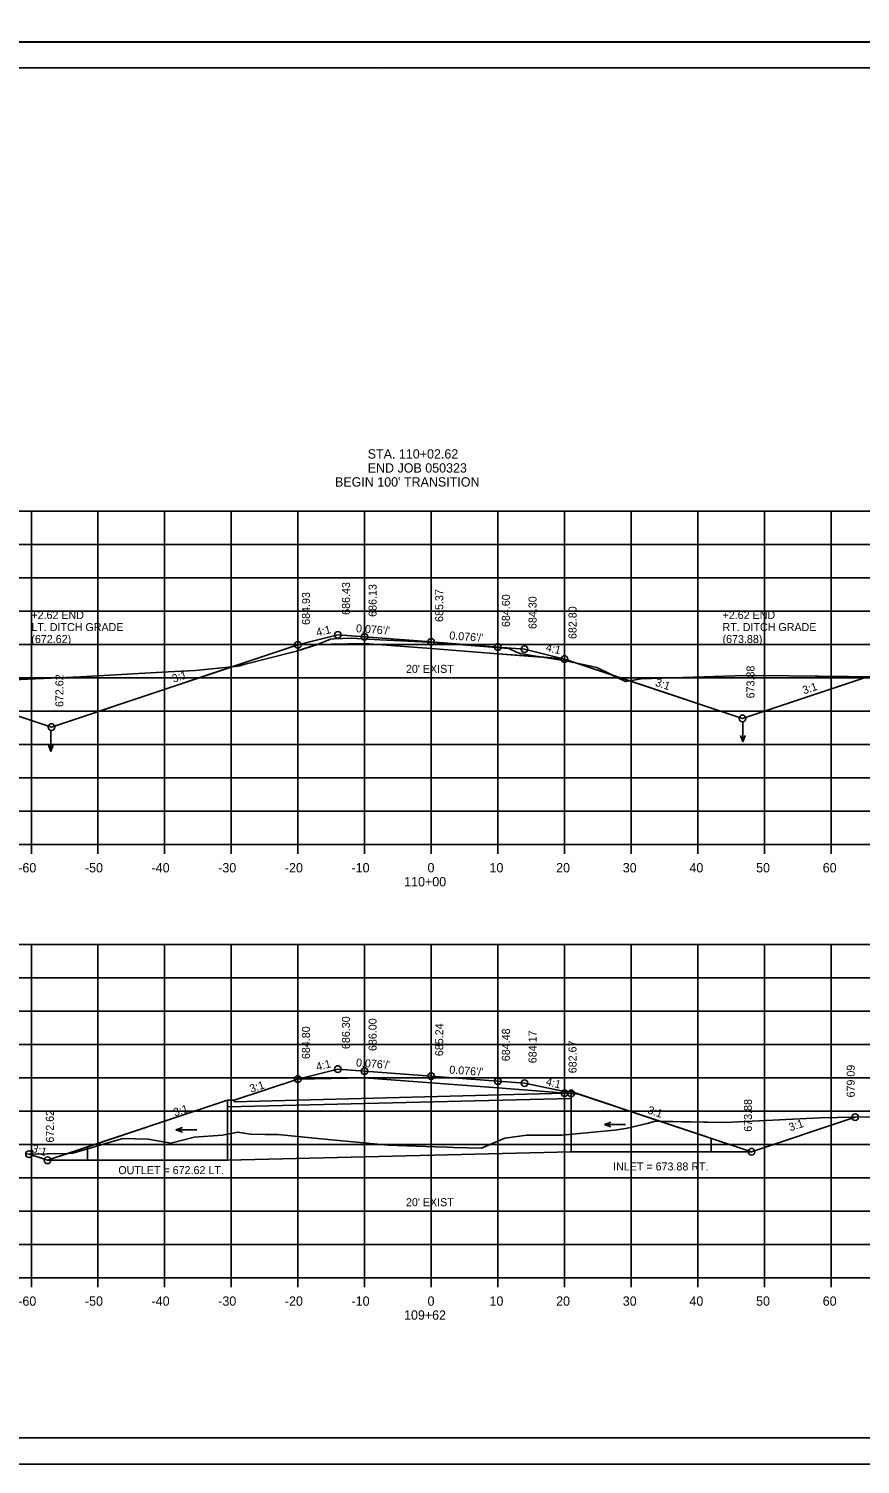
# Model space of a CAD drawing. Extents: x 1360146 to 1361431, y 631444 to 632352.
# Drawn here: x 1360258.4 to 1360383.1, y 631870.8 to 632086.2 of the extents above; entities that cross this region are included whole.
import ezdxf

# ---------------------------------------------------------------- set-up
doc = ezdxf.new("R2010")
doc.units = 0
for name, color, linetype in [('Default', 7, 'Continuous'), ('R_Alt Surface', 7, 'Continuous'), ('R_Axis', 7, 'Continuous'), ('R_Axis Annot', 7, 'Continuous'), ('R_Border', 7, 'Continuous'), ('R_Exist Surface', 7, 'Continuous'), ('R_Fin Surface', 7, 'Continuous'), ('R_Grid', 7, 'Continuous'), ('R_No Plot', 7, 'Continuous'), ('R_Water', 7, 'Continuous'), ('R_Water Annot', 7, 'Continuous'), ('R_Xsect Elev', 7, 'Continuous'), ('R_Xsect Slope', 7, 'Continuous')]:
    doc.layers.add(name, color=color, linetype=linetype)

msp = doc.modelspace()

# ---------------------------------------------------------------- linework, layer by layer
at = {"layer": 'Default'}
for p, q in [((1360308.77, 631988.16), (1360308.77, 631989.53)), ((1360308.77, 631988.82), (1360328.77, 631988.82)), ((1360328.77, 631988.16), (1360328.77, 631989.53)), ((1360332.77, 631927.99), (1360338.77, 631926.74)), ((1360288.2, 631925.43), (1360289.2, 631925.43)), ((1360366.83, 631917.72), (1360382.39, 631922.91)), ((1360308.77, 631908.16), (1360308.77, 631909.53)), ((1360308.77, 631908.82), (1360328.77, 631908.82)), ((1360328.77, 631908.16), (1360328.77, 631909.53))]:
    msp.add_line(p, q, dxfattribs=at)
at = {"layer": 'R_Alt Surface'}
for points in [[(1360298.75, 631993.74), (1360308.77, 631993.94), (1360318.77, 631993.19), (1360328.77, 631992.42), (1360338.55, 631991.67)], [(1360298.75, 631928.61), (1360308.77, 631928.81), (1360318.77, 631928.06), (1360328.77, 631927.29), (1360340.89, 631926.37)]]:
    msp.add_lwpolyline(points, dxfattribs=at)
at = {"layer": 'R_Axis'}
for p, q in [((1360178.77, 631963.82), (1360458.77, 631963.82)), ((1360258.77, 631962.42), (1360258.77, 631963.82)), ((1360268.77, 631962.42), (1360268.77, 631963.82)), ((1360278.77, 631962.42), (1360278.77, 631963.82)), ((1360288.77, 631962.42), (1360288.77, 631963.82)), ((1360298.77, 631962.42), (1360298.77, 631963.82)), ((1360308.77, 631962.42), (1360308.77, 631963.82)), ((1360318.77, 631962.42), (1360318.77, 631963.82)), ((1360328.77, 631962.42), (1360328.77, 631963.82)), ((1360338.77, 631962.42), (1360338.77, 631963.82)), ((1360348.77, 631962.42), (1360348.77, 631963.82)), ((1360358.77, 631962.42), (1360358.77, 631963.82)), ((1360368.77, 631962.42), (1360368.77, 631963.82)), ((1360378.77, 631962.42), (1360378.77, 631963.82)), ((1360178.77, 631898.82), (1360458.77, 631898.82)), ((1360258.77, 631897.42), (1360258.77, 631898.82)), ((1360268.77, 631897.42), (1360268.77, 631898.82)), ((1360278.77, 631897.42), (1360278.77, 631898.82)), ((1360288.77, 631897.42), (1360288.77, 631898.82)), ((1360298.77, 631897.42), (1360298.77, 631898.82)), ((1360308.77, 631897.42), (1360308.77, 631898.82)), ((1360318.77, 631897.42), (1360318.77, 631898.82)), ((1360328.77, 631897.42), (1360328.77, 631898.82)), ((1360338.77, 631897.42), (1360338.77, 631898.82)), ((1360348.77, 631897.42), (1360348.77, 631898.82)), ((1360358.77, 631897.42), (1360358.77, 631898.82)), ((1360368.77, 631897.42), (1360368.77, 631898.82)), ((1360378.77, 631897.42), (1360378.77, 631898.82))]:
    msp.add_line(p, q, dxfattribs=at)
at = {"layer": 'R_Border'}
for p, q in [((1360158.77, 632080.28), (1360474.95, 632080.28)), ((1360311.29, 632080.02), (1360311.29, 632080.02)), ((1360311.29, 632080.02), (1360311.29, 632080.02)), ((1360474.95, 631874.82), (1360158.77, 631874.82))]:
    msp.add_line(p, q, dxfattribs=at)
at = {"layer": 'R_Exist Surface'}
for points in [[(1360236.74, 631987.68), (1360260.53, 631988.72), (1360260.57, 631988.72), (1360260.61, 631988.72), (1360266.15, 631988.93), (1360279.32, 631989.69), (1360283.36, 631989.88), (1360289.35, 631990.49), (1360290.04, 631990.61), (1360290.65, 631990.81), (1360298.57, 631992.8), (1360301.69, 631993.82), (1360303.67, 631994.61), (1360304.16, 631994.65), (1360306.77, 631994.73), (1360311.04, 631994.52), (1360318.39, 631994.15), (1360322.84, 631993.81), (1360330.41, 631993.2), (1360331.57, 631992.65), (1360332.16, 631992.47), (1360334.1, 631992.09), (1360339.03, 631991.36), (1360343.63, 631990.34), (1360347.93, 631988.25), (1360350.29, 631988.65), (1360365.94, 631989.14), (1360372.41, 631989.11), (1360390.37, 631988.9)], [(1360258.06, 631917.36), (1360264.29, 631917.44), (1360265, 631917.52), (1360272.51, 631919.69), (1360276.32, 631919.58), (1360279.68, 631919.01), (1360283.22, 631919.92), (1360287.46, 631920.21), (1360289.76, 631920.67), (1360291.64, 631920.33), (1360293.78, 631920.28), (1360295.75, 631920.3), (1360302.24, 631919.66), (1360312.29, 631918.68), (1360319.35, 631918.47), (1360321.14, 631918.41), (1360322.11, 631918.37), (1360326.32, 631918.24), (1360329.8, 631919.77), (1360333.12, 631920.2), (1360333.65, 631920.19), (1360338.39, 631920.2), (1360346.26, 631920.97), (1360347.95, 631921.21), (1360351.15, 631921.96), (1360352.42, 631922.28), (1360362.86, 631922.12), (1360377.14, 631922.78), (1360387.04, 631923.01)]]:
    msp.add_lwpolyline(points, dxfattribs=at)
at = {"layer": 'R_Fin Surface'}
for points in [[(1360242.28, 631987.92), (1360261.78, 631981.42), (1360298.75, 631993.74), (1360298.77, 631993.75), (1360304.77, 631995.25), (1360308.77, 631994.95), (1360318.77, 631994.19), (1360328.77, 631993.42), (1360332.77, 631993.12), (1360338.55, 631991.67), (1360338.77, 631991.62), (1360365.47, 631982.72), (1360384.22, 631988.97)], [(1360258.42, 631917.36), (1360261.2, 631916.43), (1360288.2, 631925.43), (1360289.2, 631925.43), (1360298.75, 631928.61), (1360298.77, 631928.62), (1360304.77, 631930.12), (1360308.77, 631929.82), (1360318.77, 631929.06), (1360328.77, 631928.3), (1360332.77, 631927.99), (1360338.77, 631926.74), (1360339.77, 631926.74), (1360366.83, 631917.72), (1360382.39, 631922.91)]]:
    msp.add_lwpolyline(points, dxfattribs=at)
at = {"layer": 'R_Grid'}
for p, q in [((1360178.77, 632013.82), (1360458.77, 632013.82)), ((1360258.77, 631963.82), (1360258.77, 632013.82)), ((1360268.77, 631963.82), (1360268.77, 632013.82)), ((1360278.77, 631963.82), (1360278.77, 632013.82)), ((1360288.77, 631963.82), (1360288.77, 632013.82)), ((1360298.77, 631963.82), (1360298.77, 632013.82)), ((1360308.77, 631963.82), (1360308.77, 632013.82)), ((1360318.77, 631963.82), (1360318.77, 632013.82)), ((1360328.77, 631963.82), (1360328.77, 632013.82)), ((1360338.77, 631963.82), (1360338.77, 632013.82)), ((1360348.77, 631963.82), (1360348.77, 632013.82)), ((1360358.77, 631963.82), (1360358.77, 632013.82)), ((1360368.77, 631963.82), (1360368.77, 632013.82)), ((1360378.77, 631963.82), (1360378.77, 632013.82)), ((1360178.77, 632008.82), (1360458.77, 632008.82)), ((1360178.77, 632003.82), (1360458.77, 632003.82)), ((1360178.77, 631998.82), (1360458.77, 631998.82)), ((1360178.77, 631993.82), (1360458.77, 631993.82)), ((1360178.77, 631988.82), (1360458.77, 631988.82)), ((1360178.77, 631983.82), (1360458.77, 631983.82)), ((1360178.77, 631978.82), (1360458.77, 631978.82)), ((1360178.77, 631973.82), (1360458.77, 631973.82)), ((1360178.77, 631968.82), (1360458.77, 631968.82)), ((1360178.77, 631963.82), (1360458.77, 631963.82)), ((1360178.77, 631948.82), (1360458.77, 631948.82)), ((1360258.77, 631898.82), (1360258.77, 631948.82)), ((1360268.77, 631898.82), (1360268.77, 631948.82)), ((1360278.77, 631898.82), (1360278.77, 631948.82)), ((1360288.77, 631898.82), (1360288.77, 631948.82)), ((1360298.77, 631898.82), (1360298.77, 631948.82)), ((1360308.77, 631898.82), (1360308.77, 631948.82)), ((1360318.77, 631898.82), (1360318.77, 631948.82)), ((1360328.77, 631898.82), (1360328.77, 631948.82)), ((1360338.77, 631898.82), (1360338.77, 631948.82)), ((1360348.77, 631898.82), (1360348.77, 631948.82)), ((1360358.77, 631898.82), (1360358.77, 631948.82)), ((1360368.77, 631898.82), (1360368.77, 631948.82)), ((1360378.77, 631898.82), (1360378.77, 631948.82)), ((1360178.77, 631943.82), (1360458.77, 631943.82)), ((1360178.77, 631938.82), (1360458.77, 631938.82)), ((1360178.77, 631933.82), (1360458.77, 631933.82)), ((1360178.77, 631928.82), (1360458.77, 631928.82)), ((1360178.77, 631923.82), (1360458.77, 631923.82)), ((1360178.77, 631918.82), (1360458.77, 631918.82)), ((1360178.77, 631913.82), (1360458.77, 631913.82)), ((1360178.77, 631908.82), (1360458.77, 631908.82)), ((1360178.77, 631903.82), (1360458.77, 631903.82)), ((1360178.77, 631898.82), (1360458.77, 631898.82))]:
    msp.add_line(p, q, dxfattribs=at)
at = {"layer": 'R_No Plot'}
for p, q in [((1360146.37, 632084.18), (1360479.7, 632084.18)), ((1360146.37, 632084.17), (1360479.7, 632084.17)), ((1360146.37, 631870.84), (1360479.7, 631870.84))]:
    msp.add_line(p, q, dxfattribs=at)
for points in [[(1360146.36, 632297.51), (1360479.7, 632297.51), (1360479.7, 632084.17), (1360146.36, 632084.17)], [(1360146.36, 632084.17), (1360479.7, 632084.17), (1360479.7, 631870.84), (1360146.36, 631870.84)], [(1360392.69, 632080.28), (1360392.69, 632070.4), (1360428.42, 632070.4), (1360428.42, 632067.48), (1360451.62, 632067.48), (1360451.62, 632043.15), (1360474.95, 632043.15), (1360474.95, 631874.82), (1360158.77, 631874.82), (1360158.77, 632080.28)], [(1360288.84, 631990.44), (1360289.35, 631990.49), (1360290.04, 631990.61), (1360290.65, 631990.81), (1360298.57, 631992.8), (1360301.63, 631993.8), (1360298.75, 631993.74)], [(1360301.63, 631993.8), (1360301.69, 631993.82), (1360303.67, 631994.61), (1360304.16, 631994.65), (1360306.77, 631994.73), (1360311.04, 631994.52), (1360318.39, 631994.15), (1360322.84, 631993.81), (1360330.41, 631993.2), (1360331.57, 631992.65), (1360332.16, 631992.47), (1360334.1, 631992.09), (1360335.14, 631991.94), (1360328.77, 631992.42), (1360318.77, 631993.19), (1360308.77, 631993.94)], [(1360335.14, 631991.94), (1360339.03, 631991.36), (1360340.59, 631991.02), (1360338.77, 631991.62), (1360338.55, 631991.67)], [(1360340.59, 631991.02), (1360343.63, 631990.34), (1360345.83, 631989.27)], [(1360242.28, 631987.92), (1360260.53, 631988.72), (1360260.57, 631988.72), (1360260.61, 631988.72), (1360266.15, 631988.93), (1360279.32, 631989.69), (1360283.36, 631989.88), (1360288.84, 631990.44), (1360261.78, 631981.42)], [(1360345.83, 631989.27), (1360347.93, 631988.25), (1360348.56, 631988.36)], [(1360348.56, 631988.36), (1360350.29, 631988.65), (1360365.94, 631989.14), (1360372.41, 631989.11), (1360384.22, 631988.97), (1360365.47, 631982.72)], [(1360264.23, 631917.44), (1360264.29, 631917.44), (1360265, 631917.52), (1360272.51, 631919.69), (1360276.32, 631919.58), (1360279.68, 631919.01), (1360283.22, 631919.92), (1360287.46, 631920.21), (1360289.76, 631920.67), (1360291.64, 631920.33), (1360293.78, 631920.28), (1360295.75, 631920.3), (1360302.24, 631919.66), (1360312.29, 631918.68), (1360319.35, 631918.47), (1360321.14, 631918.41), (1360322.11, 631918.37), (1360326.32, 631918.24), (1360329.8, 631919.77), (1360333.12, 631920.2), (1360333.65, 631920.19), (1360338.39, 631920.2), (1360346.26, 631920.97), (1360347.95, 631921.21), (1360351.15, 631921.96), (1360352.42, 631922.28), (1360353.18, 631922.27), (1360340.89, 631926.37), (1360328.77, 631927.29), (1360318.77, 631928.06), (1360308.77, 631928.81), (1360298.75, 631928.61), (1360289.2, 631925.43), (1360288.2, 631925.43)], [(1360353.18, 631922.27), (1360362.86, 631922.12), (1360377.14, 631922.78), (1360382.39, 631922.91), (1360366.83, 631917.72)], [(1360258.42, 631917.36), (1360264.23, 631917.44), (1360261.2, 631916.43)]]:
    msp.add_lwpolyline(points, close=True, dxfattribs=at)
for centre in [(1360304.77, 631995.25), (1360308.77, 631994.95), (1360298.77, 631993.75), (1360318.77, 631994.19), (1360328.77, 631993.42), (1360332.77, 631993.12), (1360338.77, 631991.62), (1360365.47, 631982.72), (1360261.78, 631981.42), (1360304.77, 631930.12), (1360298.77, 631928.62), (1360308.77, 631929.82), (1360318.77, 631929.06), (1360328.77, 631928.3), (1360332.77, 631927.99), (1360338.77, 631926.49), (1360339.77, 631926.47), (1360382.39, 631922.91), (1360258.42, 631917.36), (1360366.83, 631917.72), (1360261.2, 631916.43)]:
    msp.add_circle(centre, 0.5, dxfattribs=at)
at = {"layer": 'R_Water'}
for p, q in [((1360338.77, 631926.49), (1360289.2, 631925.18)), ((1360338.77, 631926.49), (1360338.77, 631926.74)), ((1360338.77, 631926.74), (1360339.77, 631926.74)), ((1360338.77, 631926.74), (1360339.77, 631926.74)), ((1360366.83, 631917.72), (1360339.77, 631926.74)), ((1360339.77, 631917.74), (1360339.77, 631926.74)), ((1360261.2, 631916.43), (1360288.2, 631925.43)), ((1360339.77, 631925.72), (1360288.2, 631924.47)), ((1360288.2, 631916.43), (1360288.2, 631925.43)), ((1360289.2, 631925.18), (1360289.2, 631925.43)), ((1360360.77, 631917.74), (1360360.77, 631919.74)), ((1360267.2, 631916.43), (1360267.2, 631918.43)), ((1360339.77, 631917.72), (1360288.2, 631916.43)), ((1360339.77, 631917.72), (1360366.83, 631917.72)), ((1360258.42, 631917.36), (1360261.2, 631916.43)), ((1360261.2, 631916.43), (1360288.2, 631916.43))]:
    msp.add_line(p, q, dxfattribs=at)
at = {"layer": 'R_Water Annot'}
for p, q in [((1360365.5, 631982.32), (1360365.5, 631979.18)), ((1360261.7, 631980.91), (1360261.7, 631977.77)), ((1360365.5, 631979.18), (1360365.15, 631980.14)), ((1360365.5, 631979.18), (1360365.85, 631980.14)), ((1360261.7, 631977.77), (1360261.35, 631978.73)), ((1360261.7, 631977.77), (1360262.05, 631978.73)), ((1360344.76, 631921.79), (1360345.72, 631922.14)), ((1360347.91, 631921.79), (1360344.76, 631921.79)), ((1360344.76, 631921.79), (1360345.72, 631921.44)), ((1360280.47, 631920.99), (1360281.43, 631921.34)), ((1360283.61, 631920.99), (1360280.47, 631920.99)), ((1360280.47, 631920.99), (1360281.43, 631920.64))]:
    msp.add_line(p, q, dxfattribs=at)

# ---------------------------------------------------------------- texts
at = {"layer": 'Default'}
for s, p in [('+2.62 END', (1360258.77, 631997.62)), ('+2.62 END', (1360362.48, 631997.62)), ('(672.62)', (1360258.77, 631994.02)), ('LT. DITCH GRADE', (1360258.77, 631995.82)), ('(673.88)', (1360362.48, 631994.02)), ('RT. DITCH GRADE', (1360362.48, 631995.82)), ("20' EXIST", (1360314.98, 631989.55)), ("20' EXIST", (1360314.98, 631909.55))]:
    msp.add_text(s, height=1.2, dxfattribs=at).set_placement(p)
at = {"layer": 'R_Axis Annot'}
for s, p in [('STA. 110+02.62', (1360309.24, 632021.69)), ('END JOB 050323', (1360309.24, 632019.59)), ("BEGIN 100' TRANSITION", (1360304.33, 632017.49)), ('-60', (1360256.81, 631959.62)), ('-50', (1360266.81, 631959.62)), ('-40', (1360276.81, 631959.62)), ('-30', (1360286.81, 631959.62)), ('-20', (1360296.81, 631959.62)), ('-10', (1360306.81, 631959.62)), ('0', (1360318.21, 631959.62)), ('10', (1360327.51, 631959.62)), ('20', (1360337.51, 631959.62)), ('30', (1360347.51, 631959.62)), ('40', (1360357.51, 631959.62)), ('50', (1360367.51, 631959.62)), ('60', (1360377.51, 631959.62)), ('110+00', (1360314.71, 631957.52)), ('-60', (1360256.81, 631894.62)), ('-50', (1360266.81, 631894.62)), ('-40', (1360276.81, 631894.62)), ('-30', (1360286.81, 631894.62)), ('-20', (1360296.81, 631894.62)), ('-10', (1360306.81, 631894.62)), ('0', (1360318.21, 631894.62)), ('10', (1360327.51, 631894.62)), ('20', (1360337.51, 631894.62)), ('30', (1360347.51, 631894.62)), ('40', (1360357.51, 631894.62)), ('50', (1360367.51, 631894.62)), ('60', (1360377.51, 631894.62)), ('109+62', (1360314.69, 631892.52))]:
    msp.add_text(s, height=1.4, dxfattribs=at).set_placement(p)
at = {"layer": 'R_Water Annot'}
for s, p in [('OUTLET = 672.62 LT.', (1360271.82, 631914.36)), ('INLET = 673.88 RT.', (1360346.06, 631914.91))]:
    msp.add_text(s, height=1.2, dxfattribs=at).set_placement(p)
at = {"layer": 'R_Xsect Elev'}
for s, p in [('684.93', (1360300.57, 631996.75)), ('686.43', (1360306.57, 631998.25)), ('686.13', (1360310.57, 631997.95)), ('685.37', (1360320.57, 631997.19)), ('684.60', (1360330.57, 631996.42)), ('684.30', (1360334.57, 631996.12)), ('682.80', (1360340.57, 631994.62)), ('672.62', (1360263.58, 631984.42)), ('673.88', (1360367.27, 631985.72)), ('686.30', (1360306.57, 631933.12)), ('686.00', (1360310.57, 631932.82)), ('685.24', (1360320.57, 631932.06)), ('684.80', (1360300.57, 631931.62)), ('684.48', (1360330.57, 631931.3)), ('684.17', (1360334.57, 631930.99)), ('682.67', (1360340.57, 631929.49)), ('679.09', (1360382.31, 631925.86)), ('672.62', (1360262.15, 631919.09)), ('673.88', (1360366.89, 631920.72))]:
    msp.add_text(s, height=1.2, rotation=90, dxfattribs=at).set_placement(p)
at = {"layer": 'R_Xsect Slope'}
for s, rotation, p in [('4:1', 14.0362, (1360301.65, 631994.99)), ("0.076'/'", 355.6497, (1360307.45, 631995.65)), ("0.076'/'", 355.6497, (1360321.45, 631994.58)), ('4:1', 345.9638, (1360335.89, 631992.86)), ('3:1', 18.4349, (1360280.12, 631988.06)), ('3:1', 341.5651, (1360352.28, 631987.64)), ('3:1', 18.4349, (1360374.69, 631986.32)), ('4:1', 14.0362, (1360301.65, 631929.86)), ("0.076'/'", 355.6497, (1360307.45, 631930.52)), ("0.076'/'", 355.6497, (1360321.45, 631929.46)), ('3:1', 18.4349, (1360291.75, 631926.55)), ('4:1', 345.9638, (1360335.89, 631927.73)), ('3:1', 18.4349, (1360280.31, 631923)), ('3:1', 341.5651, (1360351.13, 631923.5)), ('3:1', 18.4349, (1360372.64, 631920.77)), ('3:1', 341.5651, (1360258.74, 631917.74))]:
    msp.add_text(s, height=1.2, rotation=rotation, dxfattribs=at).set_placement(p)

doc.saveas('drawing.dxf')
